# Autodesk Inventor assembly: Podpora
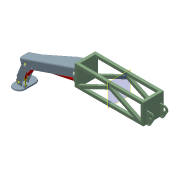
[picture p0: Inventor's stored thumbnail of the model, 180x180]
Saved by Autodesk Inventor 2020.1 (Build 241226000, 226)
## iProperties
Manager: www.cadconsulting.pl
Company: Fabian Stasiak CAD Consulting
Created: 2005-10
Part Number: Podpora
Document SubType Name: Assembly
Designer: F.Stasiak
Author: F.Stasiak
Subject: Zbiór ćwiczeń. Autodesk Inventor 2020. Kurs podstawowy
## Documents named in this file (3)
- C:\2020_Kurs_podstawowy\R6 Zespoły\Lustro\Podpora.iam
- C:\2020_Kurs_podstawowy\R6 Zespoły\Lustro\Rama.ipt
- C:\2020_Kurs_podstawowy\R6 Zespoły\Lustro\Ramię.iam
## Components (2 placed, 2 different names)
1. Rama:1 — Wstaw:1, Wstaw:2, Wstaw:3, Kąt:1
2. Ramię:1 [sub-assembly] — Wstaw:1, Wstaw:2, Wstaw:3, Kąt:1
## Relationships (4: Insert 3, Angle 1)
- Wstaw:1 [Insert]: Rama:1 ↔ Ramię:1
- Wstaw:2 [Insert]: Rama:1 ↔ Ramię:1
- Wstaw:3 [Insert]: Rama:1 ↔ Ramię:1
- Kąt:1 [Angle]: Rama:1 ↔ Ramię:1
